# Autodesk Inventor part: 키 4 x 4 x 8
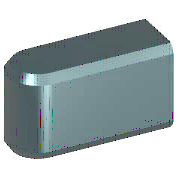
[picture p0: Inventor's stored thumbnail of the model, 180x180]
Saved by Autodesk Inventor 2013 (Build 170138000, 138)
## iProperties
Created: 2012-02
Part Number: 키 4 x 4 x 8
Material: 강철, 연강
Description: 키 및 해당 키홈
Document SubType Name: Modeling
Standard: KS B 1311
Designer: mduedu
Standards Organization: KS
Language: ko-KR
Size Designation: 4 x 4 x 8
Categories: <MemberInstance><Categories><Category DisplayName="샤프트 부품" InternalName="7f7aeb1f-a693-4053-b835-cee3144e0d98" Mnemonic="SHFT"><Category DisplayName="키" Interna
Density: 7.86 g/cm^3
Mass: 0.94325 g
Surface Area: 1.44138 cm^2
Volume: 0.120006 cm^3
IsCustomPart: 1
Author: mduedu
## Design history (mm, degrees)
sketch "스케치1"
  geometry: L1 (2, 2)-(8, 2); L2 (8, 2)-(8, -2); L3 (8, -2)-(2, -2); L4 (0, 7)-(0, -7) reference; L5 (-5, 0)-(30, 0) reference; A1 r 2 centre (2, 0) between (2, 2) and (2, -2)
  constraints: 6 end point, 3 tangent, 2 point on circle, 1 centre point, 1 horizontal, 1 parallel, 1 perpendicular, 1 point on line
  dimensions: "d0" = 2 radius of A1 (= 0.5 x PB); "d7" = 8 distance between parallel lines of L2 L4 (= NLG)
workplane "Work Plane1"
workplane "Work Plane2"
extrude "본체1" new body sketch "스케치1" taper "d3" = 0 deg; stored distance "d4" = 10
workaxis "Work Axis1"
workplane "Work Plane4"
body "Solid1"
chamfer "모따기1" distance "d8" = 0.25 (= PHH); stored, may be unused: second distance "d9" = 0.25 (= PHH), angle "d13" = 45 deg
other parameters: "d1" = -2.5 (= -PNT), "d2" = 1.5 (= PH - PNT), "NLG" = 8 [user parameter; used in 2 equation terms], "PB" = 4 [user parameter; used in 1 equation term], "PNT" = 2.5 [user parameter; used in 2 equation terms], "PH" = 4 [user parameter; used in 1 equation term], "PHH" = 0.25 [user parameter; used in 2 equation terms], "d10" = 0, "d16" = 0, "d17" = 0, "d18" = 0, "RR" = 0.08 [user parameter], "WDMAX" = 12 [user parameter], "PLB1" = 8 (= NLG) [user parameter], "PUEB" = 1.8 [user parameter]
